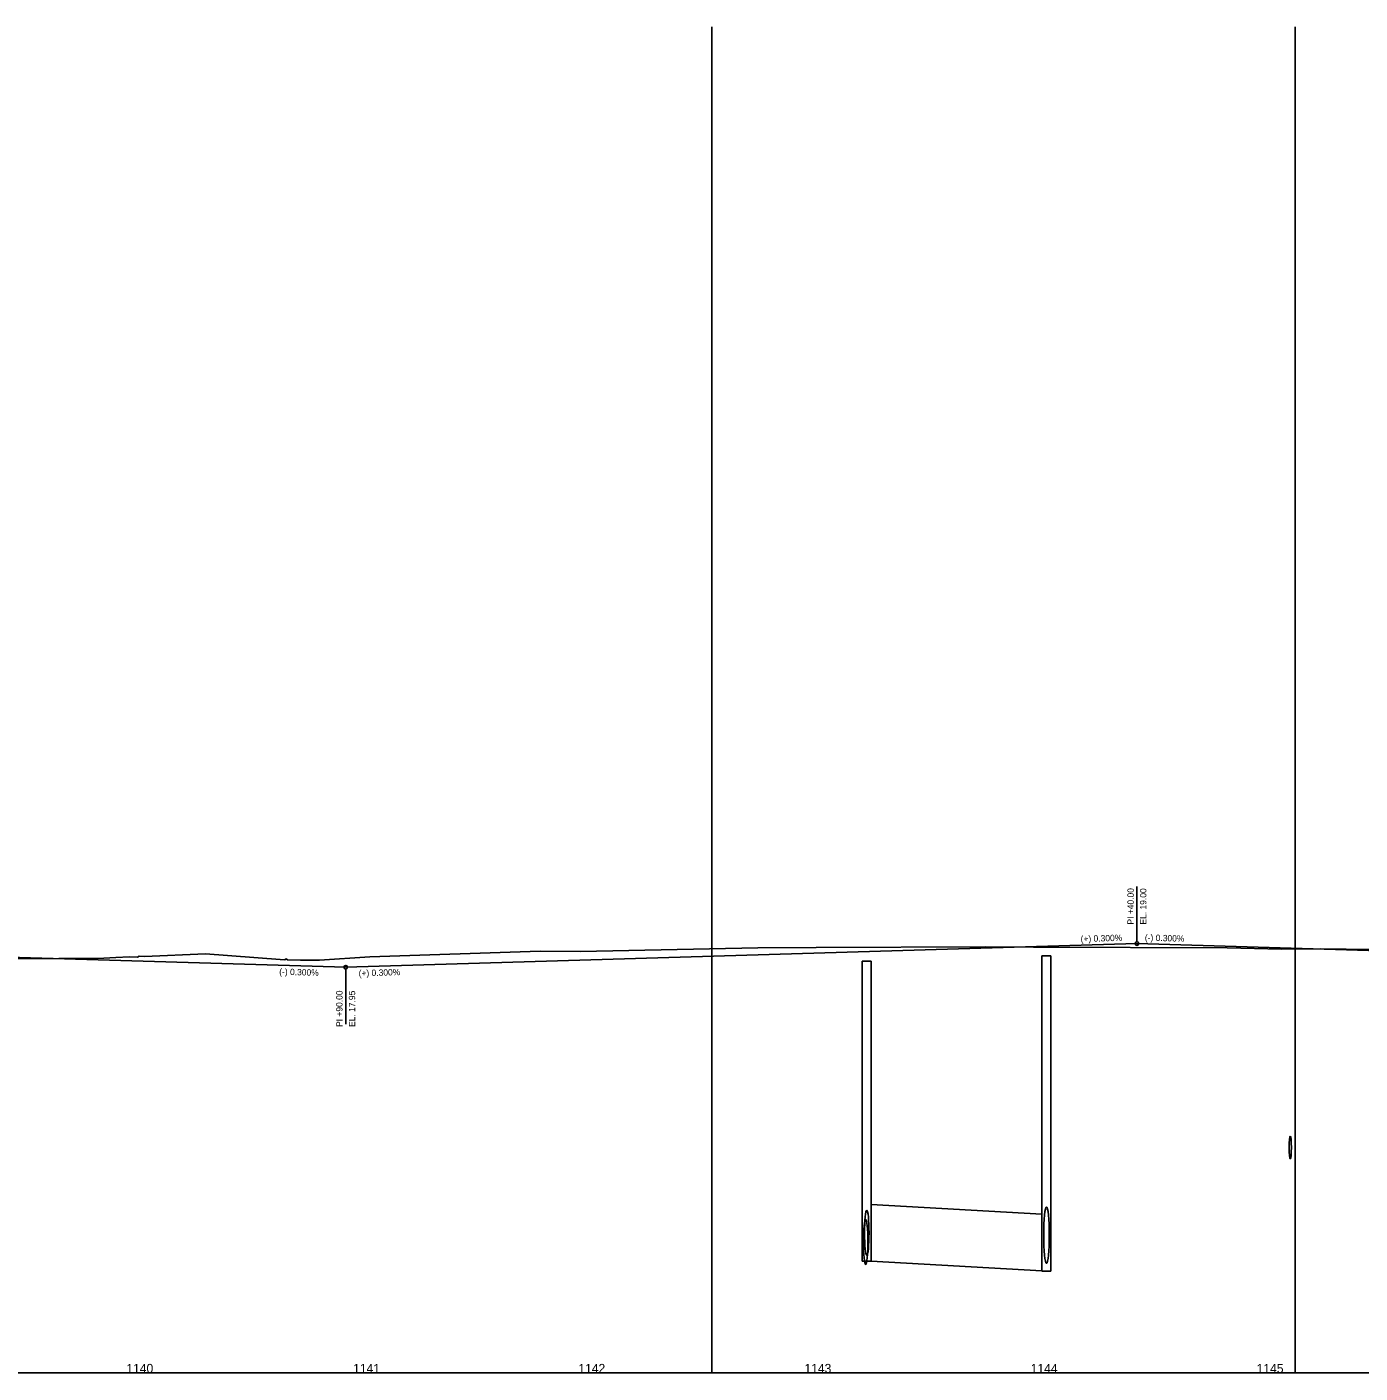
# Model space of a CAD drawing. Extents: x 1409 to 6106, y -2180 to -1584.
# Drawn here: x 3760 to 4349, y -2180 to -1584 of the extents above; entities that cross this region are included whole.
import ezdxf

# ---------------------------------------------------------------- set-up
doc = ezdxf.new("R2010")
doc.units = 0
for name, color, linetype in [('CLConst_dp', 7, 'Continuous'), ('DrainStruct_pr', 7, 'Continuous'), ('LaneLine', 7, 'Continuous'), ('NonPlottingEle_dp', 7, 'Continuous'), ('PipeCulvert_ep', 7, 'Continuous'), ('PipeCulvert_pr', 7, 'Continuous'), ('PipeCulvert_px', 7, 'Continuous'), ('StationTicS_dp', 7, 'Continuous'), ('TextLabel', 7, 'Continuous'), ('TextProfLabel', 7, 'Continuous'), ('TextPtLabel', 7, 'Continuous')]:
    doc.layers.add(name, color=color, linetype=linetype)

msp = doc.modelspace()

# ---------------------------------------------------------------- linework, layer by layer
at = {"layer": 'CLConst_dp'}
msp.add_line((1410.73, -2179.71), (6032.47, -2179.71), dxfattribs=at)
at = {"layer": 'DrainStruct_pr'}
for p, q in [((4208.68, -1995.21), (4208.68, -2031.61)), ((4208.68, -1995.21), (4208.68, -2031.61)), ((4212.68, -1995.21), (4212.68, -2031.61)), ((4212.68, -1995.21), (4212.68, -2031.61)), ((4129.18, -1997.51), (4129.18, -2033.91)), ((4129.18, -1997.51), (4129.18, -2033.91)), ((4133.18, -1997.51), (4133.18, -2033.91)), ((4133.18, -1997.51), (4133.18, -2033.91)), ((4129.18, -2033.91), (4129.18, -2130.21)), ((4133.18, -2033.91), (4133.18, -2069.11)), ((4133.18, -2033.91), (4133.18, -2130.21)), ((4208.68, -2031.61), (4208.68, -2134.71)), ((4212.68, -2031.61), (4212.68, -2066.81)), ((4212.68, -2031.61), (4212.68, -2134.71)), ((4129.18, -2130.21), (4133.18, -2130.21)), ((4208.68, -2134.71), (4212.68, -2134.71))]:
    msp.add_line(p, q, dxfattribs=at)
for centre, major_axis in [((4131.23, -2117.71), (0, 10)), ((4210.73, -2118.71), (0, 12.5))]:
    msp.add_ellipse(centre, major_axis=major_axis, ratio=0.1, dxfattribs=at)
at = {"layer": 'NonPlottingEle_dp'}
for p, q in [((4250.73, -1988.91), (4250.73, -1964.51)), ((3900.73, -2001.01), (3900.73, -2025.41))]:
    msp.add_line(p, q, dxfattribs=at)
for centre in [(4250.73, -1989.71), (3900.73, -2000.21)]:
    msp.add_circle(centre, 0.8, dxfattribs=at)
at = {"layer": 'PipeCulvert_ep'}
for centre, major_axis in [((4318.56, -2079.93), (0, 5)), ((4130.72, -2121.71), (0, 10))]:
    msp.add_ellipse(centre, major_axis=major_axis, ratio=0.1, dxfattribs=at)
at = {"layer": 'PipeCulvert_pr'}
for p, q in [((4212.68, -1995.21), (4208.68, -1995.21)), ((4133.18, -1997.51), (4129.18, -1997.51))]:
    msp.add_line(p, q, dxfattribs=at)
at = {"layer": 'PipeCulvert_px'}
for p, q in [((4133.18, -2105.14), (4208.68, -2109.5)), ((4133.18, -2130.21), (4208.68, -2134.57))]:
    msp.add_line(p, q, dxfattribs=at)
at = {"layer": 'StationTicS_dp'}
msp.add_lwpolyline([(3753.84, -1996.48), (3793.77, -1996.12), (3798.99, -1995.94), (3805.15, -1995.6), (3808.6, -1995.81), (3809.4, -1995.32), (3811.81, -1995.45), (3838.77, -1994.31), (3871.82, -1996.7), (3873.82, -1996.87), (3874.42, -1996.5), (3874.96, -1996.9), (3880.81, -1997.04), (3885.28, -1997.11), (3889.15, -1997.14), (3911.43, -1995.59), (3986.83, -1993.12), (4004.57, -1993.21), (4083.07, -1991.6), (4108.86, -1991.48), (4183.87, -1991.18), (4204.95, -1991.25), (4290.67, -1991.61), (4314.64, -1992.22), (4331.73, -1992.04), (4389.1, -1992.78)], dxfattribs=at)
msp.add_lwpolyline([(3753.84, -1996.48), (3793.77, -1996.12), (3798.99, -1995.94), (3805.15, -1995.6), (3808.6, -1995.81), (3809.4, -1995.32), (3811.81, -1995.45), (3838.77, -1994.31), (3871.82, -1996.7), (3873.82, -1996.87), (3874.42, -1996.5), (3874.96, -1996.9), (3880.81, -1997.04), (3885.28, -1997.11), (3889.15, -1997.14), (3911.43, -1995.59), (3986.83, -1993.12), (4004.57, -1993.21), (4083.07, -1991.6), (4108.86, -1991.48), (4183.87, -1991.18), (4204.95, -1991.25), (4290.67, -1991.61), (4314.64, -1992.22), (4331.73, -1992.04), (4389.1, -1992.78)], dxfattribs=at)
at = {"layer": 'TextLabel'}
for p, q in [((4062.73, -2179.71), (4062.73, -1584.14)), ((4320.73, -2179.71), (4320.73, -1584.14))]:
    msp.add_line(p, q, dxfattribs=at)
at = {"layer": 'TextPtLabel'}
for p, q in [((3650.73, -1992.71), (3900.73, -2000.21)), ((3900.73, -2000.21), (4250.73, -1989.71)), ((4250.73, -1989.71), (4530.73, -1998.11))]:
    msp.add_line(p, q, dxfattribs=at)

# ---------------------------------------------------------------- texts
at = {"layer": 'LaneLine'}
for s, rotation, p in [('(+) 0.300%', 1.71836, (4225.86, -1989.06)), ('(-) 0.300%', 358.28164, (4254.2, -1988.42)), ('(-) 0.300%', 358.28164, (3871.3, -2003.5)), ('(+) 0.300%', 1.71836, (3906.5, -2004.25))]:
    msp.add_text(s, height=2.8, rotation=rotation, dxfattribs=at).set_placement(p)
at = {"layer": 'NonPlottingEle_dp'}
for s, p in [('PI +40.00', (4249.33, -1981.31)), ('EL. 19.00', (4254.93, -1981.31)), ('PI +90.00', (3899.33, -2026.61)), ('EL. 17.95', (3904.93, -2026.61))]:
    msp.add_text(s, height=2.8, rotation=90, dxfattribs=at).set_placement(p)
at = {"layer": 'TextProfLabel'}
for s, p in [('1140', (3803.71, -2179.71)), ('1141', (3904.02, -2179.71)), ('1142', (4003.66, -2179.71)), ('1143', (4103.66, -2179.71)), ('1144', (4203.74, -2179.71)), ('1145', (4303.68, -2179.71))]:
    msp.add_text(s, height=4, dxfattribs=at).set_placement(p)

doc.saveas('drawing.dxf')
